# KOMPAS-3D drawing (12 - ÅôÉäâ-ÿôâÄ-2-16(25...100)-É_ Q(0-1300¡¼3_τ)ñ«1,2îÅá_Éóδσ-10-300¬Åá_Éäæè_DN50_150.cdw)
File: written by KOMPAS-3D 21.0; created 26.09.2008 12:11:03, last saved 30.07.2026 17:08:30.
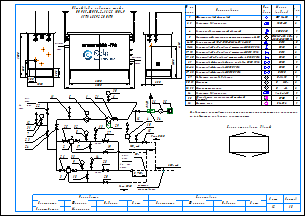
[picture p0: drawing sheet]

Sheets 1-2: A3, landscape

Document properties: Наименование: Макро:21; Автор: RaskoAdmin; Форматы листов документа: 2xA3; Полное имя файла: \\ur38nt01\Departments\КТО\КБ ПУРДГ\Заявки\Прайс-лист на типовые шкафы ГРПШ\ПУРДГ_стандарт_30_04_2026\ПУРДГ с РДСК\ПУРДГ-ШУГО-2-16(25...100)-Р_ Q(0-1300нм3_ч)до1,2МПа_Рвых-10-300кПа_РДСК_DN50_150.cdw

Title block, sheet 1: Наименование: Пункт учета газа / ПУГ-Ш-400-Р / ЛГТИ.485922.001ТУ; designation: ЛГТИ.03.4411141; sheet number: 1; Количество листов документа: 2; organisation: ООО "ЭЛЬСТЕР Газэлектроника"; Форматы листов документа: A3; stored path: C:\Рабочие документы\Компас\ПУГ\Схема.cdw; Разработал: Устинов; Проверил: Кошкин; Утвердил: Кошкин
Title block, sheet 2: sheet number: 2; stored path: D:\Рабочие документы\Заявки\ПУРДГ\ПУРДГ-ШУЭО-2-100-Р 4411220.cdw; designation, second copy: ЛГТИ.03.4411141-

Views: Вид 1, Вид 2
Referenced files: wcvoit.frw
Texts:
  Normal
  DN150
  Выход газа
  DN50
  Вход газа
  logo-rasko-ge.png
  DN 1
  местное
  сопротивление
  Римп DN20
  Выход
  газа
  Р=     кПа
  Вход
  Р=       МПа
  PDI
  Общий вид и габариты шкафа
  ПУРДГ-ШУГО-2-16(25...100)-Р
  № на
  схеме
  Усл.
  обозн.
  Марка
  (модель)
  Кол.
  Фильтр газовый фланцевый
  ФГ 16-50
  Регулятор давления газа
  РДСК-50
  Клапан предохранительный сбросной
  КПС DN20
  Измерительный комплекс с ротационным счетчиком Ду50
  СГ-ЭК-Р-(0,2...2,0)-
  Кран кнопочный VE-РАСКО-НЗ-1,6-G1/2-М20
  DN15
  Кран шаровой "под приварку" штуцерный DN20 PN16
  DN20
  Кран шаровой "под приварку" штуцерный DN15 PN16
  Кран шаровой "под приварку" штуцерный п/п DN20 PN16
  Кран шаровой фланцевый с мех. приводом DN50 PN16
  Кран шаровой фланцевый DN50 PN16
  Кран шаровой фланцевый DN150 PN16
  Индикатор перепада давления
  Манометр
  Манометр-напоромер
  Обогреватель газогорелочный шкафной
  (Эльтон")
  Счетчик газа
  Delta 15
  0...     МПа
  0...     кПа
  Venio-A-15
  ОГШН
  BK-G1,6
  Схема открывания дверей
  Предприятие изготовитель может заменять комплектующие на аналогичные,
  не ухудшающие заявленных характеристик.
  Должность
  Конструктор
  Фамилия
  Подпись
  Дата
  Согласовано
  Максимкин
  Лист
  Листов
  POLYLINE_STYLE_0.18_RGB_0_0_0
  POLYLINE_STYLE_0.50_RGB_0_0_0
  POLYLINE_STYLE_0.34_RGB_0_0_0
  PHANTOM_RGB_0_0_0_SC_1_THICK_0.18
  K5LT_THIN_RGB_0_0_0_THICK_0.18
  K5LT32769_RGB_0_0_0_THICK_0.18
  K5LT12_RGB_0_0_0_SC_1_THICK_0.18
  K5LT_DASHED_RGB_0_0_0_SC_1_THICK_0.18
  ACISOTGL_RGB_0_0_0_SC_0.8_THICK_0.25
  CONTINUOUS_RGB_0_127_31_THICK_0.3
  CONTINUOUS_RGB_0_0_255_THICK_0.35
  CONTINUOUS_RGB_255_0_0_THICK_0.35
  POLYLINE_STYLE_0.25_RGB_0_0_0
  CONTINUOUS_RGB_0_0_0_THICK_0.5
  POLYLINE_STYLE_0.35_RGB_0_0_255
  CONTINUOUS_RGB_0_0_0_THICK_0.4
  CONTINUOUS_RGB_0_0_0_THICK_0.35
  НЕВИДИМАЯ_RGB_0_0_0_SC_0.3_THICK_0.25
  СONTINUOUS_RGB_0_0_0_THICK_0.25
  ОСЕВАЯ2_RGB_248_153_30_SC_0.3_THICK_0.25
  Без оформления
Dimensions and other numbers on the sheet: 1; 1500; 250; 300; 1050; 550; 305; 2500; 4130; 2000; 2800; 5,,,7DN 1; 7; 31; 12; 22; 23; 24; 11; 5; 21; 6; 30; 25; 32; 8; 2; 17; 13; 27; 19; 4; 10; 15; 26; 33; 9; 3; 18; 14; 28; 20; 29; 2, 3; 6-10; 11-16; 17, 18; 19, 20; 22-26; 27, 28; 30, 31; 32, 33; 34; 35; 36; 16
